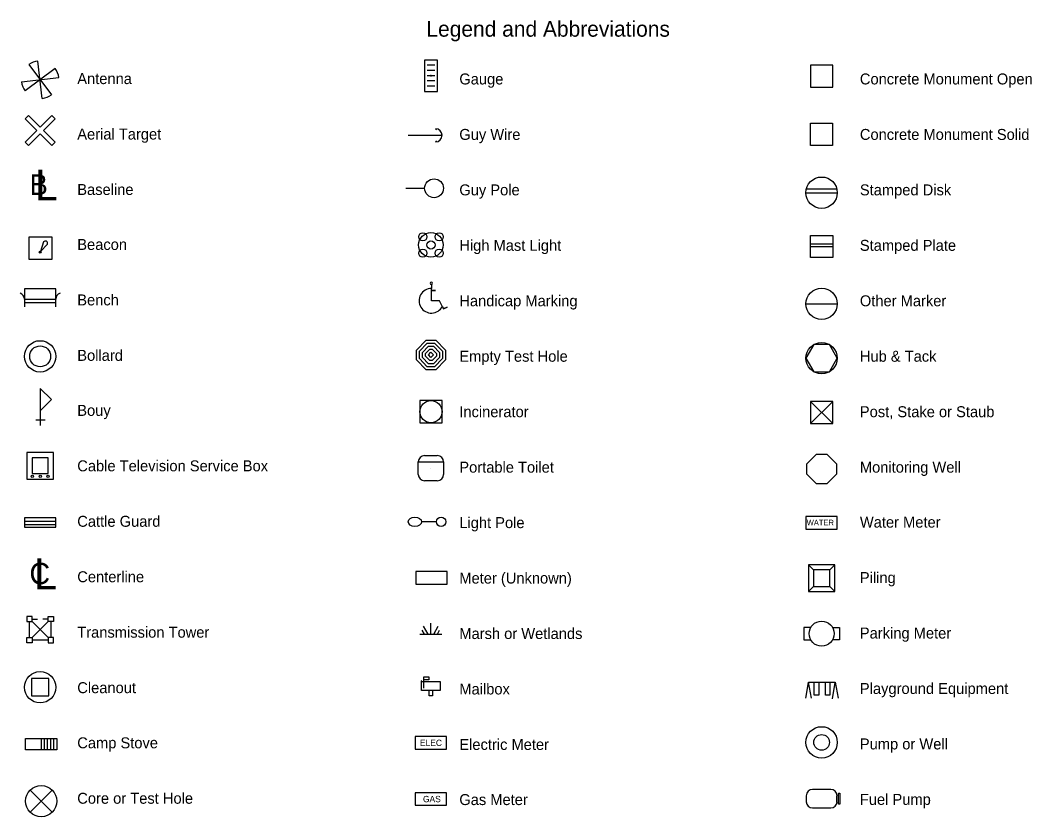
# Model space of a CAD drawing. Extents: x -371 to 730, y -9 to 425.
# Drawn here: x -371.2 to -209.8, y 297.5 to 424.6 of the extents above; entities that cross this region are included whole.
import ezdxf

# ---------------------------------------------------------------- set-up
doc = ezdxf.new("R2010")
doc.units = 0
for name, color, linetype in [('Beacons_ep', 7, 'Continuous'), ('BLSurveySymbl_ep', 7, 'Continuous'), ('Bollard_ep', 7, 'Continuous'), ('BusStop_ep', 7, 'Continuous'), ('CattleGuard_ep', 7, 'Continuous'), ('CATVMisc_ep', 7, 'Continuous'), ('CLConst_dp', 7, 'Continuous'), ('Core_ep', 7, 'Continuous'), ('Furnace_ep', 7, 'Continuous'), ('Gauges_ep', 7, 'Continuous'), ('Guys_ep', 7, 'Continuous'), ('Hole_ep', 7, 'Continuous'), ('Luminaire_ep', 7, 'Continuous'), ('Mailbox_ep', 7, 'Continuous'), ('MeterElec_ep', 7, 'Continuous'), ('MeterGas_ep', 7, 'Continuous'), ('MeterUnk_ep', 7, 'Continuous'), ('MeterWater_ep', 7, 'Continuous'), ('MiscEquip_ep', 7, 'Continuous'), ('Monument_ep', 7, 'Continuous'), ('ParkEquip_ep', 7, 'Continuous'), ('Pavemk_ep', 7, 'Continuous'), ('Piling_ep', 7, 'Continuous'), ('Pump_ep', 7, 'Continuous'), ('PumpNonPet_ep', 7, 'Continuous'), ('SanitaryMisc_ep', 7, 'Continuous'), ('StreamMisc_ep', 7, 'Continuous'), ('Tower_ep', 7, 'Continuous'), ('Wells_ep', 7, 'Continuous'), ('WetlandSym_ep', 7, 'Continuous')]:
    doc.layers.add(name, color=color, linetype=linetype)

# ---------------------------------------------------------------- blocks, each defined once
blk = doc.blocks.new('BL')
at = {"layer": 'BLSurveySymbl_ep'}
for s, height, p in [('B', 0.0813, (-0.0223, -0.036)), ('L', 0.1221, (-0.0007, -0.0578))]:
    blk.add_text(s, height=height, dxfattribs=at).set_placement(p)
blk = doc.blocks.new('BN')
at = {"layer": 'Beacons_ep'}
blk.add_lwpolyline([(-1.76, -1.17), (-1.76, 2.43), (1.84, 2.43), (1.84, -1.17)], close=True, dxfattribs=at)
blk.add_lwpolyline([(0.55, 1.63), (0.08, 0.12), (1.15, 1.28)], dxfattribs=at)
for radius in [0.148, 0.116, 0.0806, 0.0483, 0.0211]:
    blk.add_circle((0, 0), radius, dxfattribs=at)
blk.add_arc((0.84, 1.43), 0.348, 334.5119, 145.7032, dxfattribs=at)
blk = doc.blocks.new('CL')
at = {"layer": 'CLConst_dp'}
for s, height, p in [('C', 0.0852, (-0.0427, -0.0432)), ('L', 0.1234, (-0.0245, -0.0637))]:
    blk.add_text(s, height=height, dxfattribs=at).set_placement(p)
blk = doc.blocks.new('POINT_DISPLAY')
blk.add_line((0, 0), (0, 0))

msp = doc.modelspace()

# ---------------------------------------------------------------- linework, layer by layer
at = {"layer": 'Bollard_ep'}
for radius in [2.5, 1.67]:
    msp.add_circle((-368.04, 370.95), radius, dxfattribs=at)
at = {"layer": 'BusStop_ep'}
for p, q in [((-370.54, 380.06), (-365.54, 380.06)), ((-370.54, 379.56), (-370.54, 378.83)), ((-365.54, 378.83), (-365.54, 379.56))]:
    msp.add_line(p, q, dxfattribs=at)
msp.add_lwpolyline([(-370.54, 379.56), (-365.54, 379.56), (-365.54, 381.74), (-370.54, 381.74), (-370.54, 380.06), (-370.54, 379.56)], close=True, dxfattribs=at)
for centre, start, end in [((-371.59, 380.06), 0.2359, 69.1544), ((-364.49, 380.06), 110.8456, 179.7641)]:
    msp.add_arc(centre, 1.05, start, end, dxfattribs=at)
at = {"layer": 'CattleGuard_ep'}
msp.add_lwpolyline([(-365.54, 345.17), (-370.54, 345.17), (-370.54, 343.68), (-365.54, 343.68)], close=True, dxfattribs=at)
for points in [[(-370.54, 344.66), (-365.54, 344.66)], [(-370.54, 344.14), (-365.54, 344.14)]]:
    msp.add_lwpolyline(points, dxfattribs=at)
at = {"layer": 'CATVMisc_ep'}
for points in [[(-370.16, 351.33), (-365.89, 351.33), (-365.89, 355.61), (-370.16, 355.61), (-370.16, 351.33)], [(-369.3, 352.26), (-366.78, 352.26), (-366.78, 354.78), (-369.3, 354.78), (-369.3, 352.26)]]:
    msp.add_lwpolyline(points, dxfattribs=at)
for centre in [(-369.29, 351.79), (-368.03, 351.79), (-366.78, 351.79)]:
    msp.add_circle(centre, 0.186, dxfattribs=at)
at = {"layer": 'Core_ep'}
for p, q in [((-369.64, 298.2), (-366.11, 301.74)), ((-369.64, 301.74), (-366.11, 298.2))]:
    msp.add_line(p, q, dxfattribs=at)
msp.add_circle((-367.87, 299.97), 2.5, dxfattribs=at)
at = {"layer": 'Furnace_ep'}
msp.add_lwpolyline([(-303.93, 360.34), (-303.93, 363.88), (-307.46, 363.88), (-307.46, 360.34)], close=True, dxfattribs=at)
msp.add_circle((-305.7, 362.11), 1.77, dxfattribs=at)
at = {"layer": 'Gauges_ep'}
for p, q in [((-305.07, 417.41), (-306.32, 417.41)), ((-305.07, 416.58), (-306.32, 416.58)), ((-305.07, 415.74), (-306.32, 415.74)), ((-305.07, 414.91), (-306.32, 414.91)), ((-305.07, 414.08), (-306.32, 414.08))]:
    msp.add_line(p, q, dxfattribs=at)
msp.add_lwpolyline([(-304.65, 418.24), (-306.74, 418.24), (-306.74, 413.24), (-304.65, 413.24)], close=True, dxfattribs=at)
msp.add_circle((-305.7, 415.74), 0.0833, dxfattribs=at)
at = {"layer": 'Guys_ep'}
for p, q in [((-304.96, 407.27), (-304.8, 407.11)), ((-303.91, 406.2), (-309.31, 406.2)), ((-304.8, 405.32), (-304.96, 405.17)), ((-309.7, 397.77), (-306.7, 397.77))]:
    msp.add_line(p, q, dxfattribs=at)
msp.add_circle((-305.2, 397.77), 1.5, dxfattribs=at)
msp.add_arc((-304.96, 406.22), 1.05, 270, 90, dxfattribs=at)
at = {"layer": 'Hole_ep'}
for points in [[(-306.48, 373.53), (-304.91, 373.53), (-303.37, 371.96), (-303.37, 370.4), (-304.91, 368.82), (-306.48, 368.82), (-308.02, 370.4), (-308.02, 371.96)], [(-306.28, 373.05), (-305.11, 373.05), (-303.84, 371.77), (-303.84, 370.59), (-305.11, 369.3), (-306.28, 369.3), (-307.54, 370.59), (-307.54, 371.77)], [(-306.08, 372.58), (-305.31, 372.58), (-304.32, 371.57), (-304.32, 370.79), (-305.31, 369.78), (-306.08, 369.78), (-307.06, 370.79), (-307.06, 371.57)], [(-305.88, 372.1), (-305.51, 372.1), (-304.8, 371.38), (-304.8, 370.98), (-305.51, 370.26), (-305.87, 370.26), (-306.58, 370.98), (-306.58, 371.38)], [(-305.69, 371.6), (-305.28, 371.18), (-305.28, 371.18), (-305.69, 370.76), (-306.1, 371.18), (-306.1, 371.18)]]:
    msp.add_lwpolyline(points, close=True, dxfattribs=at)
at = {"layer": 'Luminaire_ep'}
msp.add_line((-304.82, 344.56), (-307.2, 344.56), dxfattribs=at)
msp.add_circle((-304.07, 344.56), 0.749, dxfattribs=at)
msp.add_ellipse((-308.26, 344.56), major_axis=(1.06, 0), ratio=0.705882, dxfattribs=at)
at = {"layer": 'Mailbox_ep'}
for points in [[(-306.84, 317.98), (-306.84, 319.82), (-306.02, 319.82), (-306.02, 319.3), (-306.84, 319.3)], [(-307.2, 319.02), (-307.2, 319.05), (-304.2, 319.05), (-304.2, 317.6), (-307.2, 317.6), (-307.2, 319.02), (-307.22, 319.15), (-307.28, 319.15)], [(-305.44, 317.6), (-305.44, 316.79), (-305.96, 316.79), (-305.96, 317.6)]]:
    msp.add_lwpolyline(points, dxfattribs=at)
at = {"layer": 'MeterElec_ep'}
msp.add_lwpolyline([(-308.2, 308.27), (-303.2, 308.27), (-303.2, 310.27), (-308.2, 310.27)], close=True, dxfattribs=at)
at = {"layer": 'MeterGas_ep'}
msp.add_lwpolyline([(-308.2, 299.31), (-303.2, 299.31), (-303.2, 301.31), (-308.2, 301.31)], close=True, dxfattribs=at)
at = {"layer": 'MeterUnk_ep'}
msp.add_lwpolyline([(-308.12, 334.61), (-303.12, 334.61), (-303.12, 336.61), (-308.12, 336.61)], close=True, dxfattribs=at)
at = {"layer": 'MeterWater_ep'}
msp.add_lwpolyline([(-245.87, 343.39), (-240.87, 343.39), (-240.87, 345.39), (-245.87, 345.39)], close=True, dxfattribs=at)
at = {"layer": 'MiscEquip_ep'}
msp.add_line((-307.71, 354.1), (-303.68, 354.1), dxfattribs=at)
for points in [[(-306.71, 355.12), (-306.71, 355.12), (-304.69, 355.12), (-304.69, 355.12)], [(-307.71, 352.1), (-307.71, 352.09), (-307.71, 354.12), (-307.71, 354.11)], [(-303.68, 354.11), (-303.68, 354.12), (-303.68, 352.09), (-303.68, 352.1)], [(-304.69, 351.09), (-304.69, 351.09), (-306.71, 351.09), (-306.71, 351.09)], [(-245.1, 327.7), (-246.19, 327.7), (-246.19, 325.7), (-245.1, 325.7)], [(-241.63, 327.7), (-240.54, 327.7), (-240.54, 325.7), (-241.63, 325.7)]]:
    msp.add_lwpolyline(points, dxfattribs=at)
msp.add_circle((-243.37, 326.7), 2, dxfattribs=at)
for centre, start, end in [((-306.71, 354.11), 90, 180), ((-304.69, 354.11), 0, 90), ((-306.71, 352.1), 180, 270), ((-304.69, 352.1), 270, 0)]:
    msp.add_arc(centre, 1.01, start, end, dxfattribs=at)
at = {"layer": 'Monument_ep'}
for p, q in [((-245.87, 397.07), (-240.87, 397.07)), ((-245.79, 397.7), (-240.94, 397.7)), ((-245.13, 388.92), (-241.6, 388.92)), ((-245.13, 388.48), (-241.6, 388.48)), ((-245.87, 379.33), (-240.87, 379.33)), ((-245.13, 360.22), (-241.6, 363.76)), ((-245.13, 363.76), (-241.6, 360.22))]:
    msp.add_line(p, q, dxfattribs=at)
for points in [[(-245.13, 417.43), (-245.13, 413.89), (-241.6, 413.89), (-241.6, 417.43)], [(-245.16, 408.15), (-241.62, 408.15), (-241.62, 404.62), (-245.16, 404.62)], [(-241.6, 386.71), (-245.13, 386.71), (-245.13, 390.25), (-241.6, 390.25)], [(-244.62, 372.82), (-245.87, 370.66), (-244.62, 368.49), (-242.12, 368.49), (-240.87, 370.66), (-242.12, 372.82)], [(-245.13, 363.76), (-245.13, 360.22), (-241.6, 360.22), (-241.6, 363.76)]]:
    msp.add_lwpolyline(points, close=True, dxfattribs=at)
msp.add_lwpolyline([(-369.9, 404.62), (-368.04, 406.48), (-366.18, 404.62), (-365.66, 405.14), (-367.52, 407), (-365.66, 408.86), (-366.18, 409.39), (-368.04, 407.53), (-369.9, 409.39), (-370.42, 408.86), (-368.56, 407), (-370.42, 405.14), (-369.9, 404.62)], dxfattribs=at)
for centre in [(-243.37, 397.07), (-243.37, 379.33), (-243.37, 370.66)]:
    msp.add_circle(centre, 2.5, dxfattribs=at)
at = {"layer": 'ParkEquip_ep'}
for points in [[(-245.89, 316.38), (-245.44, 318.9)], [(-245, 316.41), (-245.44, 318.94), (-241.2, 318.94), (-240.75, 316.38)], [(-243.84, 318.94), (-243.84, 316.9), (-244.58, 316.9), (-244.58, 318.94)], [(-242.05, 318.94), (-242.05, 316.9), (-242.77, 316.9), (-242.77, 318.94)], [(-241.66, 316.31), (-241.19, 318.92)], [(-367.87, 309.98), (-367.87, 308.17)], [(-367.4, 309.98), (-367.4, 308.17)], [(-366.91, 309.98), (-366.91, 308.17)], [(-366.4, 309.98), (-366.4, 308.17)], [(-365.89, 309.98), (-365.89, 308.17)]]:
    msp.add_lwpolyline(points, dxfattribs=at)
msp.add_lwpolyline([(-370.37, 309.98), (-365.37, 309.98), (-365.37, 308.17), (-370.37, 308.17)], close=True, dxfattribs=at)
at = {"layer": 'Pavemk_ep'}
for points in [[(-305.63, 382.42), (-305.63, 381.77)], [(-303.88, 378.92), (-303.68, 378.51), (-303.09, 378.8), (-303.68, 378.51), (-304.33, 379.81), (-305.63, 379.81), (-305.63, 381.45), (-304.98, 381.45), (-305.63, 381.45), (-305.63, 381.77)]]:
    msp.add_lwpolyline(points, dxfattribs=at)
for centre, radius, start, end in [((-305.63, 382.61), 0.195, 90, 270), ((-305.63, 382.61), 0.195, 270, 90), ((-305.63, 379.81), 1.96, 89.9998, 211.5497), ((-305.63, 379.81), 1.96, 211.5497, 333.0996)]:
    msp.add_arc(centre, radius, start, end, dxfattribs=at)
at = {"layer": 'Piling_ep'}
for p, q in [((-245.49, 337.68), (-244.69, 336.89)), ((-242.04, 336.89), (-241.24, 337.68)), ((-244.69, 334.24), (-245.49, 333.44)), ((-241.24, 333.44), (-242.04, 334.24))]:
    msp.add_line(p, q, dxfattribs=at)
for points in [[(-245.49, 337.68), (-245.49, 333.44), (-241.24, 333.44), (-241.24, 337.68)], [(-244.69, 336.89), (-244.69, 334.24), (-242.04, 334.24), (-242.04, 336.89)]]:
    msp.add_lwpolyline(points, close=True, dxfattribs=at)
at = {"layer": 'Pump_ep'}
for points in [[(-241.9, 301.82), (-244.83, 301.82)], [(-245.82, 300.84), (-245.82, 299.86)], [(-240.92, 299.86), (-240.92, 300.84)], [(-244.83, 298.88), (-241.9, 298.88)]]:
    msp.add_lwpolyline(points, dxfattribs=at)
msp.add_lwpolyline([(-240.48, 301.22), (-240.48, 299.47), (-240.7, 299.47), (-240.7, 301.22)], close=True, dxfattribs=at)
for centre, start, end in [((-244.83, 300.84), 90, 180), ((-241.9, 300.84), 360, 90), ((-244.83, 299.86), 180, 270), ((-241.9, 299.86), 270, 0)]:
    msp.add_arc(centre, 0.985, start, end, dxfattribs=at)
at = {"layer": 'PumpNonPet_ep'}
for radius in [2.5, 2.5, 1.25]:
    msp.add_circle((-243.37, 309.35), radius, dxfattribs=at)
at = {"layer": 'SanitaryMisc_ep'}
msp.add_lwpolyline([(-366.65, 316.76), (-366.65, 319.53), (-369.43, 319.53), (-369.43, 316.76)], close=True, dxfattribs=at)
msp.add_circle((-368.04, 318.14), 2.5, dxfattribs=at)
at = {"layer": 'StreamMisc_ep'}
for points in [[(-368.02, 362.27), (-366.25, 364.04), (-368.02, 365.81), (-368.02, 359.93)], [(-368.71, 360.82), (-367.24, 360.82)]]:
    msp.add_lwpolyline(points, dxfattribs=at)
at = {"layer": 'Tower_ep'}
for points in [[(-367.7, 412.11), (-368.39, 418.07)], [(-365.63, 416.88), (-370.45, 413.31)], [(-369.83, 417.5), (-366.25, 412.68)], [(-371.02, 414.75), (-365.06, 415.44)], [(-370.14, 329.45), (-370.14, 328.61)], [(-369.3, 329.45), (-370.14, 329.45)], [(-369.3, 328.61), (-369.3, 329.45)], [(-366.76, 328.61), (-366.76, 329.45)], [(-366.76, 329.45), (-365.92, 329.45)], [(-365.92, 329.45), (-365.92, 328.61)], [(-370.14, 328.61), (-369.3, 328.61)], [(-369.72, 326.08), (-369.72, 328.61)], [(-369.3, 329.03), (-368.46, 329.03)], [(-366.76, 328.61), (-369.3, 326.08)], [(-369.3, 328.61), (-366.76, 326.08)], [(-366.76, 329.03), (-367.61, 329.03)], [(-365.92, 328.61), (-366.76, 328.61)], [(-366.34, 328.61), (-366.34, 326.08)], [(-370.14, 325.23), (-370.14, 326.08)], [(-370.14, 326.08), (-369.3, 326.08)], [(-369.3, 326.08), (-369.3, 325.23)], [(-365.92, 326.08), (-366.76, 326.08)], [(-366.76, 326.08), (-366.76, 325.23)], [(-365.92, 325.23), (-365.92, 326.08)], [(-369.3, 325.23), (-370.14, 325.23)], [(-366.76, 325.65), (-369.3, 325.65)], [(-366.76, 325.23), (-365.92, 325.23)]]:
    msp.add_lwpolyline(points, dxfattribs=at)
for centre, radius in [((-305.7, 388.73), 1.96), ((-307, 390.03), 0.653), ((-304.39, 390.03), 0.653), ((-305.7, 388.73), 0.653), ((-307, 387.42), 0.653), ((-304.39, 387.42), 0.653)]:
    msp.add_circle(centre, radius, dxfattribs=at)
for start, end in [(96.5864, 126.5864), (6.5864, 36.5864), (186.5864, 216.5864), (276.5864, 306.5864)]:
    msp.add_arc((-368.04, 415.09), 3, start, end, dxfattribs=at)
at = {"layer": 'Wells_ep'}
msp.add_lwpolyline([(-242.53, 355.34), (-241.01, 353.82), (-241.01, 352.15), (-242.53, 350.63), (-244.2, 350.63), (-245.72, 352.15), (-245.72, 353.82), (-244.2, 355.34)], close=True, dxfattribs=at)
at = {"layer": 'WetlandSym_ep'}
for p, q in [((-306.13, 326.63), (-306.86, 327.89)), ((-305.7, 326.63), (-305.7, 328.38)), ((-305.26, 326.63), (-304.53, 327.89)), ((-307.45, 326.63), (-303.94, 326.63)), ((-306.72, 326.63), (-307.08, 327.26)), ((-304.67, 326.63), (-304.31, 327.26))]:
    msp.add_line(p, q, dxfattribs=at)

# ---------------------------------------------------------------- block references
at = {"xscale": 40, "yscale": 40}
for name, p in [('BL', (-368.83, 398.16)), ('CL', (-368.04, 336.32))]:
    msp.add_blockref(name, p, dxfattribs=at)
msp.add_blockref('BN', (-368.04, 387.58))
at = {"layer": 'MiscEquip_ep'}
msp.add_blockref('POINT_DISPLAY', (-305.7, 353.01), dxfattribs=at)

# ---------------------------------------------------------------- texts
for s, height, p in [('Legend and Abbreviations', 2.5, (-306.42, 421.96)), ('Antenna', 1.75, (-362.12, 414.4)), ('Gauge', 1.75, (-301.17, 414.34)), ('Concrete Monument Open', 1.75, (-237.27, 414.34)), ('Aerial Target', 1.75, (-362.12, 405.55)), ('Guy Wire', 1.75, (-301.17, 405.49)), ('Concrete Monument Solid', 1.75, (-237.27, 405.49)), ('Baseline', 1.75, (-362.12, 396.7)), ('Guy Pole', 1.75, (-301.17, 396.64)), ('Stamped Disk', 1.75, (-237.27, 396.64)), ('Beacon', 1.75, (-362.12, 387.93)), ('High Mast Light', 1.75, (-301.17, 387.79)), ('Stamped Plate', 1.75, (-237.27, 387.79)), ('Bench', 1.75, (-362.12, 379.08)), ('Handicap Marking', 1.75, (-301.17, 378.94)), ('Other Marker', 1.75, (-237.27, 378.94)), ('Bollard', 1.75, (-362.12, 370.23)), ('Empty Test Hole', 1.75, (-301.17, 370.09)), ('Hub & Tack', 1.75, (-237.27, 370.09)), ('Bouy', 1.75, (-362.12, 361.45)), ('Incinerator', 1.75, (-301.17, 361.24)), ('Post, Stake or Staub', 1.75, (-237.27, 361.24)), ('Cable Television Service Box', 1.75, (-362.12, 352.6)), ('Portable Toilet', 1.75, (-301.17, 352.39)), ('Monitoring Well', 1.75, (-237.27, 352.39)), ('Cattle Guard', 1.75, (-362.12, 343.75)), ('Light Pole', 1.75, (-301.17, 343.54)), ('Water Meter', 1.75, (-237.27, 343.62)), ('Centerline', 1.75, (-362.12, 334.9)), ('Meter (Unknown)', 1.75, (-301.17, 334.69)), ('Piling', 1.75, (-237.27, 334.77)), ('Transmission Tower', 1.75, (-362.12, 326.05)), ('Marsh or Wetlands', 1.75, (-301.17, 325.84)), ('Parking Meter', 1.75, (-237.27, 325.92)), ('Cleanout', 1.75, (-362.12, 317.2)), ('Mailbox', 1.75, (-301.17, 316.99)), ('Playground Equipment', 1.75, (-237.27, 317.07)), ('Camp Stove', 1.75, (-362.12, 308.4)), ('Electric Meter', 1.75, (-301.17, 308.14)), ('Pump or Well', 1.75, (-237.27, 308.22)), ('Core or Test Hole', 1.75, (-362.12, 299.55)), ('Gas Meter', 1.75, (-301.17, 299.34)), ('Fuel Pump', 1.75, (-237.27, 299.37))]:
    msp.add_text(s, height=height).set_placement(p)
at = {"layer": 'MeterElec_ep'}
msp.add_text('ELEC', height=1.005, dxfattribs=at).set_placement((-307.45, 308.77))
at = {"layer": 'MeterGas_ep'}
msp.add_text('GAS', height=1.005, dxfattribs=at).set_placement((-306.97, 299.8))
at = {"layer": 'MeterWater_ep'}
msp.add_text('WATER', height=0.9, dxfattribs=at).set_placement((-245.75, 343.97))

doc.saveas('drawing.dxf')
